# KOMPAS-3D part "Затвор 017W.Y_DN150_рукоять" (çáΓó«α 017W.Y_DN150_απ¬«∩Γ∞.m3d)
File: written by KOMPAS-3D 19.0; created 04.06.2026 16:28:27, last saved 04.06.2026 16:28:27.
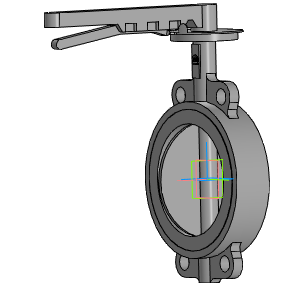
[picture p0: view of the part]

Document properties: Автор: Энергия; Полное имя файла: ..\..\..\3d для проектировщиков\017W разные\x.x Тип 017W.Y(S) Затвор дисковый поворотный межфланцевый\Затвор 017W.Y(S)_DN32-DN350_рукоять\Затвор 017W.Y_DN150_рукоять.a3d

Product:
- Part/product: Затвор 017W.Y_DN150_рукоять
    Масса: 18.4795

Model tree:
1. Операция без истории:1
